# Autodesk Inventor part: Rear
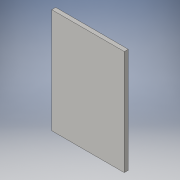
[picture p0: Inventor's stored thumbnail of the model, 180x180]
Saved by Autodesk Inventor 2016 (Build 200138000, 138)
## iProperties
Created: 2015-10
Part Number: Rear
Material: Generic
Document SubType Name: Modeling
Designer: ChombaW
Density: 1 g/cm^3
Appearance: Default
Author: ChombaW
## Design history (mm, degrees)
sketch "Sketch1"
  geometry: L1 (22.86, 33.02)-(-22.86, 33.02); L2 (-22.86, 33.02)-(-22.86, -33.02); L3 (-22.86, -33.02)-(22.86, -33.02); L4 (22.86, -33.02)-(22.86, 33.02); L5 (22.86, 33.02)-(-22.86, -33.02); L6 (-22.86, 33.02)-(22.86, -33.02); 1 further point
  constraints: 12 end point, 2 midpoint, 2 parallel, 1 horizontal, 1 perpendicular
  dimensions: "d0" = 45.72 distance of L3.end L2.end; "d1" = 66.04 distance of L2.end L1.end
extrude "Extrusion1" new body sketch "Sketch1" distance "d2" = 2.5146; taper "d3" = 0 deg
body "Solid1"
